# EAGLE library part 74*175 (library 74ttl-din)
Qadruple D type FLIP FLOP, clear
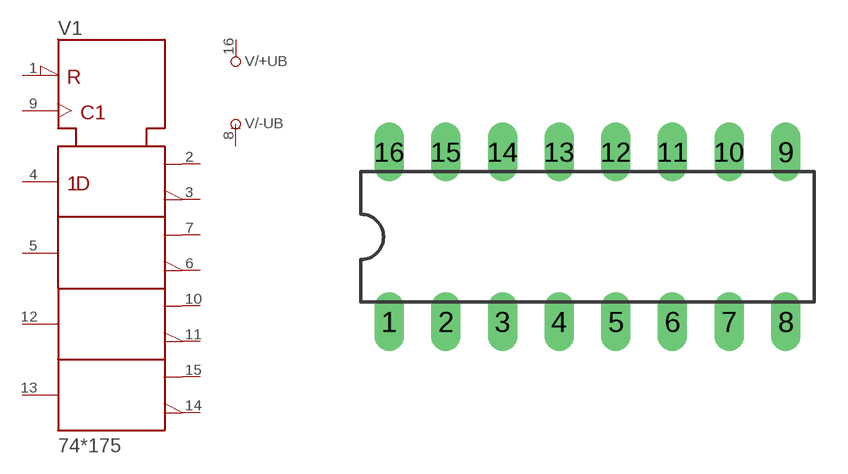
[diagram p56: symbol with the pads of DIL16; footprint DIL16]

Designator prefix V; gates /+UB=+UB /-UB=-UB 1=175

## 74175N  [DIL16]
1  1:CLR\  in
2  1:1Q  out
3  1:1Q\  out
4  1:1D  in
5  1:2D  in
6  1:2Q\  out
7  1:2Q  out
8  /-UB:-UB  pwr
9  1:CLK  in
10  1:3Q  out
11  1:3Q\  out
12  1:3D  in
13  1:4D  in
14  1:4Q\  out
15  1:4Q  out
16  /+UB:+UB  pwr

## Footprint DIL16 (pad centres in mm)
Dual In Line Package
drill 0.813 long: 1 -8.89,-3.81; 2 -6.35,-3.81; 3 -3.81,-3.81; 4 -1.27,-3.81; 5 1.27,-3.81; 6 3.81,-3.81; 7 6.35,-3.81; 8 8.89,-3.81; 9 8.89,3.81; 10 6.35,3.81; 11 3.81,3.81; 12 1.27,3.81; 13 -1.27,3.81; 14 -3.81,3.81; 15 -6.35,3.81; 16 -8.89,3.81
